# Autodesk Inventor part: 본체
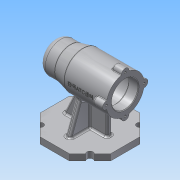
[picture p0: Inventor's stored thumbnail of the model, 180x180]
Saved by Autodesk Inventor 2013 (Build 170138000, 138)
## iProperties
Created: 2019-12
Part Number: 본체
Material: 알루미늄 6061
Document SubType Name: Modeling
Designer: Administrator
Density: 2.71 g/cm^3
Mass: 729.264 g
Surface Area: 714.585 cm^2
Volume: 269.101 cm^3
Author: Administrator
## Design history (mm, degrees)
sketch "스케치1"
  geometry: C1 r 30 at (0, 0); 1 further point
  constraints: 1 centre point, 1 coincident
  dimensions: "d0" = 60 diameter of C1
extrude "돌출1" new body sketch "스케치1" distance "d2" = 67; taper "d3" = 0 deg
sketch "스케치2"
  geometry: C1 r 30 at (0, 0) reference; C2 r 25 at (0, 0)
  constraints: 1 centre point, 1 coincident
  dimensions: "d4" = 50 diameter of C2
extrude "돌출2" join sketch "스케치2" distance "d6" = 45; taper "d7" = 0 deg
sketch "스케치3"
  geometry: L1 (25, 67)-(25, 112) reference; L2 (30, 0)-(30, 67) reference; L3 (0, 0)-(0, 126.756); L4 (25, 87)-(30, 67); L5 (30, 67)-(-30, 67) reference
  constraints: 4 end point, 1 point on line, 1 vertical
  dimensions: "d8" = 25 distance of L1.end L4.start
revolve "회전1" sketch "스케치3" stored, may be unused: angle "d9" = 90 deg
sketch "스케치4"
  geometry: C1 r 30 at (0, 0) reference; C2 r 21 at (0, 0)
  constraints: 1 centre point, 1 coincident
  dimensions: "d10" = 42 diameter of C2
extrude "돌출3" cut sketch "스케치4" distance "d12" = 15; taper "d13" = 0 deg
sketch "스케치5"
  geometry: C1 r 21 at (0, 0) reference; C2 r 24 at (0, 0)
  constraints: 1 centre point, 1 coincident
  dimensions: "d14" = 48 diameter of C2
extrude "돌출4" cut sketch "스케치5" distance "d16" = 54; taper "d17" = 0 deg
sketch "스케치6"
  geometry: C1 r 21 at (0, 0); 1 further point
  constraints: 1 centre point, 1 coincident
  dimensions: "d18" = 42 diameter of C1
extrude "돌출5" cut sketch "스케치6" distance "d20" = 12; taper "d21" = 0 deg
sketch "스케치9"
  geometry: C1 r 17.5 at (0, 0); 1 further point
  constraints: 1 centre point, 1 coincident
  dimensions: "d30" = 35 diameter of C1
extrude "돌출8" cut sketch "스케치9" distance "d32" = 18; taper "d33" = 0 deg
sketch "스케치10"
  geometry: C1 r 16 at (0, 0); 1 further point
  constraints: 1 centre point, 1 coincident
  dimensions: "d34" = 32 diameter of C1
extrude "돌출9" cut sketch "스케치10" distance "d36" = 4; taper "d37" = 0 deg
sketch "스케치11"
  geometry: C1 r 16 at (0, 0) reference; C2 r 10.5 at (0, 0)
  constraints: 1 centre point, 1 coincident
  dimensions: "d38" = 21 diameter of C2
extrude "돌출10" cut sketch "스케치11" distance "d40" = 3; taper "d41" = 0 deg
fillet "모깎기1" dims "d42" = 10
sketch "스케치12"
  geometry: A1 r 30 centre (0, 0) between (0, 30) and (-5.97, 29.4) reference; A2 r 6 centre (0, 30) between (5.97, 29.4) and (-5.97, 29.4); 1 further point
  constraints: 5 point on circle, 1 centre point, 1 vertical alignment
  dimensions: "d43" = 12 diameter of A2
extrude "돌출11" join sketch "스케치12" distance "d45" = 16; taper "d46" = 0 deg
sketch "스케치13"
  geometry: A1 r 6 centre (0, 30) between (5.97, 29.4) and (-5.97, 29.4) reference; 1 further point
  constraints: 1 coincident
hole "구멍1" sketch "스케치13" at (0, 30) diameter "d47" = 3.242; stored, may be unused: countersink angle "d51" = 90 deg, drill point angle "d53" = 118 deg; dims "d48" = 8, "d49" = 4, "d50" = 2, "d52" = 11
fillet "모깎기2" dims "d57" = 3
fillet "모깎기3" dims "d58" = 3
fillet "모깎기4" dims "d59" = 0.3
fillet "모깎기5" dims "d60" = 3
chamfer "모따기1" distance "d66" = 1; stored, may be unused: second distance "d67" = 2, angle "d68" = 45 deg
node "작업 평면1"
sketch "스케치14"
  geometry: L1 (-23.196, 0)-(-56, 32.804); L2 (-56, 32.804)-(-56, 79.196); L3 (-56, 79.196)-(-23.196, 112); L4 (-23.196, 112)-(23.196, 112); L5 (23.196, 112)-(56, 79.196); L6 (56, 79.196)-(56, 32.804); L7 (56, 32.804)-(23.196, 0); L8 (23.196, 0)-(-23.196, 0); L9 (-39.598, 95.598)-(39.598, 16.402); L10 (39.598, 95.598)-(-39.598, 16.402); L11 (-29.4, 0)-(-5.97, 0) reference; C1 r 5 at (-39.598, 16.402); C2 r 5 at (39.598, 16.402); C3 r 5 at (39.598, 95.598); C4 r 5 at (-39.598, 95.598); A1 r 56 centre (0, 56) between (-39.598, 95.598) and (39.598, 95.598); 4 further points
  constraints: 20 end point, 6 coincident, 5 centre point, 4 midpoint, 4 point on circle, 3 equal radius, 2 perpendicular, 1 collinear, 1 vertical alignment, 17 other
  dimensions: "d70" = 112 diameter of A1; "d72" = 56 distance from line of L6 A1.centre; "d73" = 90 deg angle of L10 L9 (derived); "d74" = 45 deg dimension on A1.centre L9.start point (-56, 56) (derived); "d75" = 10 diameter of C4
extrude "돌출12" join sketch "스케치14" distance "d76" = 10; taper "d77" = 0 deg
extrude "돌출13" cut sketch "스케치14" distance "d78" = 10; taper "d79" = 0 deg
node "작업 평면2"
sketch "스케치16"
  geometry: L1 (-10, -12.804)-(-56.766, 4.217); L2 (-56.766, 42.174)-(-10, 59.196); L3 (0, -32.804)-(-10, -32.804) reference; L4 (-10, -19.938)-(-10, -11.402) reference; L5 (0, 79.196)-(-10, 79.196) reference; L6 (-10, 57.794)-(-10, 66.329) reference; L7 (-10, 0)-(-10, -12.866) reference; L8 (-10, 46.392)-(-10, 0) reference; L9 (-10, 59.258)-(-10, 46.392) reference; A1 r 30 centre (-80, 23.196) between (-56.766, 4.217) and (-56.766, 42.174) reference; 1 further point
  constraints: 4 end point, 2 point on circle, 2 point on line
  dimensions: "d85" = 20 distance from line of L1.start L3; "d86" = 110 deg angle of L1 L4; "d87" = 20 distance from line of L5 L2.end; "d89" = 110 deg angle of L6 L2
extrude "돌출14" join sketch "스케치16" stored distance "d90" = 8; taper "d91" = 0 deg
sketch "스케치17"
  geometry: L1 (28.131, 74.476)-(70, 94); L2 (30, 25)-(70, 25); L3 (80, 0)-(70, 0) reference; L4 (80, 112)-(70, 112) reference; L5 (70, 112)-(70, 99.134) reference; L6 (30, 16)-(30, 66.631) reference; L7 (70, 32.804)-(70, 19.938) reference; L8 (70, 90.598)-(70, 99.134) reference; L9 (25.09, 86.642)-(29.91, 67.358) reference; 2 further points
  constraints: 4 end point, 4 point on line, 1 horizontal
  dimensions: "d92" = 25 distance between parallel lines of L2 L3; "d93" = 18 distance from line of L4 L1.end; "d95" = 115 deg angle of L8 L1
feature "리브1" dims "d96" = 1, "d97" = 8, "d98" = 0, "d99" = 0, "d100" = 1, "d101" = 1
feature "리브2" dims "d102" = 1, "d103" = 8, "d104" = 0, "d105" = 0, "d106" = 1, "d107" = 1
fillet "모깎기8" dims "d108" = 3
fillet "모깎기9" dims "d109" = 3
node "작업 평면3"
sketch "스케치19"
  geometry: L1 (-29.4, 0)-(-5.97, 0) reference; 2 further points
  constraints: 1 vertical alignment, 1 other
  dimensions: "d111" = 41 distance from line of point (0, 41) L1
feature "엠보싱1" sketch "스케치19" dims "d0" = 60, "d112" = 0.5, "d113" = 0
fillet "모깎기10" dims "d114" = 3
fillet "모깎기11" dims "d115" = 1
node "솔리드1"
pattern_circular "원형 패턴1" dims angle "d55" = 360 deg
pattern_circular "원형 패턴3" dims angle "d117" = 360 deg
other parameters: "d84" = -56, "d110" = -175.75
